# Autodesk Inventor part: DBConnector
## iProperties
Author: Charles Bliss
Shininess: 64.0
Angle Display Precision: 2
Document Length Units: 11272
Document Angle Units: 11286
Document Time Units: 11279
Document Mass Units: 11290
Document Length Units Precision: 3
Document Angle Units Precision: 2
Compacted: True
PropertySet Name: _Private Model Information
Created: 2001-12
Part Number: DBConnector
Description: Dsub 25 Pin, 2 Row, Male
Document SubType Name: Modeling
Designer: Charles Bliss
Control State: 0
Master: False
Checked Out: False
PropertySet Name: Design Tracking Control
Density: 0.0
Volumn: 0.0
Area: 0.0
PropertySet Name: Model Information
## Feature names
1. Extrusion1
2. Extrusion2
3. Fillet4
4. Pin1 [Extrusion]
5. Pin2 [Extrusion]
6. Pin50 [Extrusion]
7. Fillet1
8. Fillet2
9. Fillet50
10. Extrusion5
11. Extrusion6
12. Extrusion7
13. Extrusion8
14. ExtrudeSgr50
15. Chamfer1
16. Chamfer2
17. Chamfer50
18. Pattern1 [Rectangular Pattern]
19. Pattern2 [Rectangular Pattern]
20. Pattern50 [Rectangular Pattern]
21. Pattern15 [Rectangular Pattern]
22. Female [Extrusion]
23. Socket1 [Extrusion]
24. Socket2 [Extrusion]
25. Socket50 [Extrusion]
26. Pattern5 [Rectangular Pattern]
27. Pattern6 [Rectangular Pattern]
28. Pattern7 [Rectangular Pattern]
